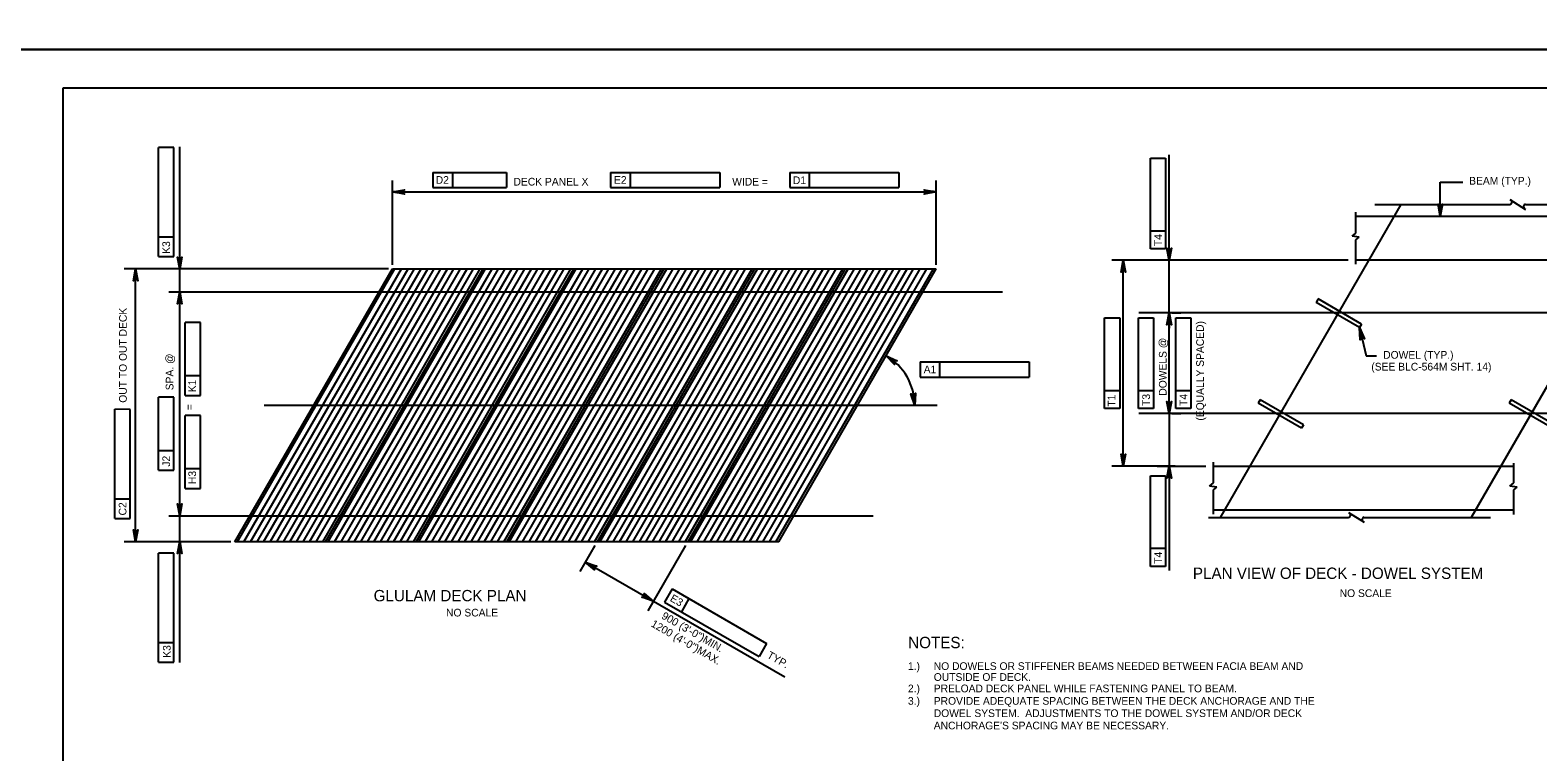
# Model space of a CAD drawing. Extents: x 638175 to 640495, y 294277 to 298435.
# Drawn here: x 639304 to 639891, y 296380 to 296661 of the extents above; entities that cross this region are included whole.
import ezdxf

# ---------------------------------------------------------------- set-up
doc = ezdxf.new("R2010")
doc.units = 0
for name, color, linetype in [('2', 7, 'Continuous'), ('3', 7, 'Continuous'), ('4', 7, 'Continuous'), ('5', 7, 'Continuous'), ('PLT-BNDY', 7, 'Continuous')]:
    doc.layers.add(name, color=color, linetype=linetype)

# ---------------------------------------------------------------- blocks, each defined once
blk = doc.blocks.new('D')
at = {"layer": '3'}
for p, q in [((-0.48575, 0.574125), (-0.574125, 0.48575)), ((0.52325, -0.6115), (-0.574125, 0.48575)), ((0.6115, -0.52325), (-0.48575, 0.574125)), ((0.6115, -0.52325), (0.52325, -0.6115))]:
    blk.add_line(p, q, dxfattribs=at)

msp = doc.modelspace()

# ---------------------------------------------------------------- linework, layer by layer
at = {"layer": '2'}
for p, q in [((639316.46, 296074.46), (639316.46, 296638.46)), ((639316.46, 296638.46), (640102.46, 296638.46)), ((639837.85, 296593.07), (639767.37, 296471.14)), ((639935.69, 296593.07), (639865.21, 296471.14)), ((639383.4, 296461.64), (639444.77, 296567.94)), ((639418.73, 296461.64), (639480.1, 296567.94)), ((639444.77, 296567.94), (639656.74, 296567.94)), ((639454.06, 296461.64), (639515.43, 296567.94)), ((639489.39, 296461.64), (639550.76, 296567.94)), ((639524.72, 296461.64), (639586.09, 296567.94)), ((639560.04, 296461.64), (639621.42, 296567.94)), ((639595.37, 296461.64), (639656.74, 296567.94)), ((639595.37, 296461.64), (639383.4, 296461.64))]:
    msp.add_line(p, q, dxfattribs=at)
at = {"layer": '3'}
for p, q in [((639880.33, 296595.01), (639886.49, 296591.14)), ((639820.34, 296581.91), (639820.34, 296590.01)), ((639820.34, 296588.45), (639937.41, 296588.45)), ((639827.73, 296593.07), (639880.26, 296593.07)), ((639886.48, 296593.07), (639938.55, 296593.07)), ((639818.8, 296580.72), (639820.34, 296581.91)), ((639821.56, 296580.3), (639818.8, 296580.72)), ((639820.34, 296579.21), (639821.56, 296580.3)), ((639820.34, 296569.79), (639820.34, 296579.21)), ((639937.41, 296571.33), (639820.34, 296571.33)), ((639926.24, 296550.81), (639735.71, 296550.84)), ((639813.03, 296550.13), (639813.82, 296551.49)), ((639790.35, 296510.9), (639791.14, 296512.26)), ((639905.36, 296511.58), (639735.7, 296511.61)), ((639764.83, 296484.54), (639764.83, 296492.64)), ((639764.83, 296491.08), (639881.91, 296491.08)), ((639881.91, 296484.54), (639881.91, 296492.27)), ((639763.29, 296483.35), (639764.83, 296484.54)), ((639766.05, 296482.93), (639763.29, 296483.35)), ((639764.83, 296481.83), (639766.05, 296482.93)), ((639880.37, 296483.35), (639881.91, 296484.54)), ((639883.12, 296482.93), (639880.37, 296483.35)), ((639881.91, 296481.83), (639883.12, 296482.93)), ((639764.83, 296472.41), (639764.83, 296481.83)), ((639881.91, 296472.22), (639881.91, 296481.83)), ((639762.88, 296471.14), (639817.36, 296471.14)), ((639881.91, 296473.95), (639764.83, 296473.95)), ((639817.43, 296473.08), (639823.59, 296469.21)), ((639823.57, 296471.14), (639872.73, 296471.14))]:
    msp.add_line(p, q, dxfattribs=at)
for centre, start, end in [((639880.26, 296593.98), 270, 60), ((639886.56, 296592.17), 95.32859, 237.86724), ((639817.36, 296472.05), 270, 60), ((639823.66, 296470.24), 95.32859, 237.86724)]:
    msp.add_arc(centre, 0.909, start, end, dxfattribs=at)
at = {"layer": '4'}
for p, q in [((639359.57, 296615.29), (639353.66, 296615.3)), ((639353.66, 296580.34), (639353.66, 296615.3)), ((639359.57, 296572.77), (639359.57, 296615.29)), ((639361.87, 296414.56), (639361.87, 296615.53)), ((639747.54, 296577.34), (639747.54, 296612.42)), ((639740.26, 296611.11), (639746.16, 296611.11)), ((639740.26, 296582.7), (639740.26, 296611.11)), ((639746.16, 296611.11), (639746.16, 296575.81)), ((639444.77, 296569.51), (639444.77, 296602.42)), ((639460.57, 296605.55), (639468.13, 296605.55)), ((639460.57, 296605.55), (639460.57, 296599.64)), ((639468.13, 296605.55), (639468.13, 296599.64)), ((639468.13, 296605.55), (639489.24, 296605.55)), ((639489.24, 296605.55), (639489.24, 296599.64)), ((639529.84, 296605.55), (639537.41, 296605.55)), ((639529.84, 296605.55), (639529.84, 296599.64)), ((639537.41, 296605.55), (639537.41, 296599.64)), ((639537.41, 296605.55), (639572.36, 296605.55)), ((639572.36, 296605.55), (639572.36, 296599.64)), ((639599.63, 296605.55), (639599.63, 296599.64)), ((639599.63, 296605.55), (639607.19, 296605.55)), ((639607.19, 296605.55), (639607.19, 296599.64)), ((639607.19, 296605.55), (639642.15, 296605.55)), ((639642.15, 296605.55), (639642.15, 296599.64)), ((639656.74, 296569.51), (639656.74, 296602.42)), ((639853.22, 296601.79), (639862.02, 296601.79)), ((639444.77, 296597.92), (639656.74, 296597.92)), ((639460.57, 296599.64), (639489.24, 296599.64)), ((639529.84, 296599.64), (639572.36, 296599.64)), ((639599.63, 296599.64), (639642.15, 296599.64)), ((639740.26, 296575.81), (639740.26, 296582.7)), ((639746.16, 296582.7), (639740.26, 296582.7)), ((639353.66, 296572.78), (639353.66, 296580.34)), ((639359.57, 296580.34), (639353.66, 296580.34)), ((639747.54, 296550.84), (639747.54, 296577.34)), ((639353.66, 296572.78), (639359.57, 296572.77)), ((639817.28, 296571.33), (639725.15, 296571.33)), ((639729.65, 296491.08), (639729.65, 296571.33)), ((639746.16, 296575.81), (639740.26, 296575.81)), ((639745.98, 296571.34), (639743.04, 296571.34)), ((639443.21, 296567.94), (639340.19, 296567.94)), ((639344.69, 296461.64), (639344.69, 296567.94)), ((639357.58, 296558.98), (639682.6, 296558.98)), ((639722.37, 296548.87), (639728.28, 296548.87)), ((639722.37, 296520.46), (639722.37, 296548.87)), ((639728.28, 296548.87), (639728.28, 296513.57)), ((639735.59, 296513.57), (639735.59, 296548.87)), ((639735.59, 296548.87), (639741.49, 296548.87)), ((639741.49, 296548.87), (639741.49, 296513.57)), ((639747.54, 296511.6), (639747.54, 296550.83)), ((639747.54, 296547.83), (639747.54, 296544.83)), ((639748.59, 296550.83), (639752.04, 296550.83)), ((639750.12, 296548.87), (639756.03, 296548.87)), ((639750.12, 296520.46), (639750.12, 296548.87)), ((639756.03, 296548.87), (639756.03, 296513.57)), ((639369.92, 296547.07), (639364.02, 296547.08)), ((639364.02, 296526.07), (639364.02, 296547.08)), ((639369.92, 296518.67), (639369.92, 296547.07)), ((639650.43, 296531.72), (639657.99, 296531.72)), ((639650.43, 296531.72), (639650.43, 296525.81)), ((639657.99, 296531.72), (639657.99, 296525.81)), ((639657.99, 296531.72), (639692.95, 296531.72)), ((639692.95, 296531.72), (639692.95, 296525.81)), ((639824.36, 296534.1), (639828.38, 296534.1)), ((639369.92, 296526.23), (639364.02, 296526.23)), ((639364.02, 296518.67), (639364.02, 296526.07)), ((639650.43, 296525.81), (639692.95, 296525.81)), ((639359.57, 296517.9), (639353.66, 296517.91)), ((639353.66, 296497.06), (639353.66, 296517.91)), ((639359.57, 296489.5), (639359.57, 296517.9)), ((639364.02, 296518.67), (639369.92, 296518.67)), ((639722.37, 296513.57), (639722.37, 296520.46)), ((639728.28, 296520.46), (639722.37, 296520.46)), ((639741.49, 296520.46), (639735.59, 296520.46)), ((639750.12, 296513.57), (639750.12, 296520.46)), ((639756.03, 296520.46), (639750.12, 296520.46)), ((639342.55, 296513.22), (639336.64, 296513.23)), ((639336.64, 296478.27), (639336.64, 296513.23)), ((639342.55, 296470.7), (639342.55, 296513.22)), ((639394.8, 296514.79), (639657.09, 296514.79)), ((639728.28, 296513.57), (639722.37, 296513.57)), ((639741.49, 296513.57), (639735.59, 296513.57)), ((639747.54, 296514.6), (639747.54, 296517.6)), ((639756.03, 296513.57), (639750.12, 296513.57)), ((639369.92, 296510.84), (639364.02, 296510.85)), ((639364.02, 296490.01), (639364.02, 296510.85)), ((639369.92, 296482.44), (639369.92, 296510.84)), ((639747.54, 296511.6), (639747.54, 296450.4)), ((639748.57, 296511.6), (639752.04, 296511.6)), ((639353.66, 296489.5), (639353.66, 296497.06)), ((639359.57, 296497.06), (639353.66, 296497.06)), ((639353.66, 296489.5), (639359.57, 296489.5)), ((639364.02, 296482.44), (639364.02, 296490.01)), ((639369.92, 296490), (639364.02, 296490.01)), ((639749.89, 296491.08), (639725.15, 296491.08)), ((639742.86, 296491.08), (639761.83, 296491.08)), ((639748.9, 296491.08), (639743.04, 296491.08)), ((639740.26, 296452.05), (639740.26, 296487.35)), ((639740.26, 296487.35), (639746.16, 296487.35)), ((639746.16, 296487.35), (639746.16, 296452.05)), ((639747.54, 296488.08), (639747.54, 296485.08)), ((639336.64, 296470.71), (639336.64, 296478.27)), ((639342.55, 296478.26), (639336.64, 296478.27)), ((639364.02, 296482.44), (639369.92, 296482.44)), ((639357.58, 296471.7), (639632.21, 296471.7)), ((639336.64, 296470.71), (639342.55, 296470.7)), ((639381.84, 296461.64), (639340.19, 296461.64)), ((639523.63, 296460.12), (639517.82, 296450.06)), ((639558.98, 296460.15), (639544.31, 296434.75)), ((639359.57, 296457.21), (639353.66, 296457.21)), ((639353.66, 296422.25), (639353.66, 296457.21)), ((639359.57, 296414.68), (639359.57, 296457.21)), ((639597.67, 296408.84), (639519.94, 296453.74)), ((639746.16, 296458.94), (639740.26, 296458.94)), ((639746.16, 296452.05), (639740.26, 296452.05)), ((639553.82, 296443.24), (639550.87, 296438.13)), ((639553.82, 296443.24), (639560.37, 296439.46)), ((639550.87, 296438.13), (639587.68, 296416.86)), ((639560.37, 296439.46), (639557.41, 296434.35)), ((639560.37, 296439.46), (639590.64, 296421.97)), ((639353.66, 296414.69), (639353.66, 296422.25)), ((639359.57, 296422.25), (639353.66, 296422.25)), ((639590.64, 296421.97), (639587.68, 296416.86)), ((639353.66, 296414.69), (639359.57, 296414.68))]:
    msp.add_line(p, q, dxfattribs=at)
for points in [[(639853.22, 296588.45), (639853.22, 296601.79)], [(639444.77, 296597.92), (639449.43, 296598.79), (639449.08, 296598.55), (639448.89, 296598.23), (639448.84, 296597.92), (639448.89, 296597.61), (639449.08, 296597.3), (639449.43, 296597.05), (639444.77, 296597.92), (639449.08, 296597.3), (639448.89, 296597.61), (639444.77, 296597.92), (639448.84, 296597.92), (639448.89, 296598.23), (639444.77, 296597.92), (639449.08, 296598.55)], [(639656.74, 296597.92), (639652.08, 296597.05), (639652.44, 296597.3), (639652.63, 296597.61), (639652.68, 296597.92), (639652.63, 296598.23), (639652.44, 296598.55), (639652.08, 296598.79), (639656.74, 296597.92), (639652.44, 296598.55), (639652.63, 296598.23), (639656.74, 296597.92), (639652.68, 296597.92), (639652.63, 296597.61), (639656.74, 296597.92), (639652.44, 296597.3)], [(639853.22, 296588.45), (639852.35, 296593.11), (639852.6, 296592.75), (639852.91, 296592.57), (639853.22, 296592.51), (639853.53, 296592.57), (639853.85, 296592.75), (639854.1, 296593.11), (639853.22, 296588.45), (639853.85, 296592.75), (639853.53, 296592.57), (639853.22, 296588.45), (639853.22, 296592.51), (639852.91, 296592.57), (639853.22, 296588.45), (639852.6, 296592.75)], [(639361.87, 296567.82), (639360.99, 296572.49), (639361.24, 296572.13), (639361.55, 296571.94), (639361.87, 296571.89), (639362.18, 296571.94), (639362.49, 296572.13), (639362.74, 296572.49), (639361.87, 296567.82), (639362.49, 296572.13), (639362.18, 296571.94), (639361.87, 296567.82), (639361.87, 296571.89), (639361.55, 296571.94), (639361.87, 296567.82), (639361.24, 296572.13)], [(639729.65, 296571.33), (639730.53, 296566.67), (639730.28, 296567.02), (639729.97, 296567.21), (639729.65, 296567.26), (639729.34, 296567.21), (639729.03, 296567.02), (639728.78, 296566.67), (639729.65, 296571.33), (639729.03, 296567.02), (639729.34, 296567.21), (639729.65, 296571.33), (639729.65, 296567.26), (639729.97, 296567.21), (639729.65, 296571.33), (639730.28, 296567.02)], [(639747.54, 296571.33), (639746.66, 296575.99), (639746.91, 296575.63), (639747.22, 296575.44), (639747.54, 296575.39), (639747.85, 296575.44), (639748.16, 296575.63), (639748.41, 296575.99), (639747.54, 296571.33), (639748.16, 296575.63), (639747.85, 296575.44), (639747.54, 296571.33), (639747.54, 296575.39), (639747.22, 296575.44), (639747.54, 296571.33), (639746.91, 296575.63)], [(639344.69, 296567.94), (639345.57, 296563.28), (639345.32, 296563.64), (639345.01, 296563.83), (639344.69, 296563.88), (639344.38, 296563.83), (639344.07, 296563.64), (639343.82, 296563.28), (639344.69, 296567.94), (639344.07, 296563.64), (639344.38, 296563.83), (639344.69, 296567.94), (639344.69, 296563.88), (639345.01, 296563.83), (639344.69, 296567.94), (639345.32, 296563.64)], [(639361.87, 296558.98), (639362.74, 296554.32), (639362.49, 296554.68), (639362.18, 296554.86), (639361.87, 296554.91), (639361.55, 296554.86), (639361.24, 296554.68), (639360.99, 296554.32), (639361.87, 296558.98), (639361.24, 296554.68), (639361.55, 296554.86), (639361.87, 296558.98), (639361.87, 296554.91), (639362.18, 296554.86), (639361.87, 296558.98), (639362.49, 296554.68)], [(639747.54, 296550.84), (639748.41, 296546.18), (639748.16, 296546.54), (639747.85, 296546.72), (639747.54, 296546.78), (639747.22, 296546.72), (639746.91, 296546.54), (639746.66, 296546.18), (639747.54, 296550.84), (639746.91, 296546.54), (639747.22, 296546.72), (639747.54, 296550.84), (639747.54, 296546.78), (639747.85, 296546.72), (639747.54, 296550.84), (639748.16, 296546.54)], [(639821.78, 296545.07), (639824.36, 296534.1)], [(639821.78, 296545.07), (639823.7, 296540.74), (639823.38, 296541.03), (639823.03, 296541.14), (639822.71, 296541.12), (639822.42, 296540.99), (639822.16, 296540.74), (639822, 296540.33), (639821.78, 296545.07), (639822.16, 296540.74), (639822.42, 296540.99), (639821.78, 296545.07), (639822.71, 296541.12), (639823.03, 296541.14), (639821.78, 296545.07), (639823.38, 296541.03)], [(639637.21, 296534.1), (639641.49, 296532.06), (639641.05, 296532.07), (639640.72, 296531.93), (639640.49, 296531.71), (639640.35, 296531.42), (639640.31, 296531.06), (639640.46, 296530.65), (639637.21, 296534.1), (639640.31, 296531.06), (639640.35, 296531.42), (639637.21, 296534.1), (639640.49, 296531.71), (639640.72, 296531.93), (639637.21, 296534.1), (639641.05, 296532.07)], [(639648.34, 296514.77), (639646.89, 296519.28), (639647.18, 296518.96), (639647.51, 296518.82), (639647.83, 296518.8), (639648.13, 296518.89), (639648.42, 296519.12), (639648.62, 296519.5), (639648.34, 296514.77), (639648.42, 296519.12), (639648.13, 296518.89), (639648.34, 296514.77), (639647.83, 296518.8), (639647.51, 296518.82), (639648.34, 296514.77), (639647.18, 296518.96)], [(639747.54, 296511.6), (639746.66, 296516.26), (639746.91, 296515.91), (639747.22, 296515.72), (639747.54, 296515.67), (639747.85, 296515.72), (639748.16, 296515.91), (639748.41, 296516.26), (639747.54, 296511.6), (639748.16, 296515.91), (639747.85, 296515.72), (639747.54, 296511.6), (639747.54, 296515.67), (639747.22, 296515.72), (639747.54, 296511.6), (639746.91, 296515.91)], [(639729.65, 296491.08), (639728.78, 296495.74), (639729.03, 296495.38), (639729.34, 296495.2), (639729.65, 296495.14), (639729.97, 296495.2), (639730.28, 296495.38), (639730.53, 296495.74), (639729.65, 296491.08), (639730.28, 296495.38), (639729.97, 296495.2), (639729.65, 296491.08), (639729.65, 296495.14), (639729.34, 296495.2), (639729.65, 296491.08), (639729.03, 296495.38)], [(639747.54, 296491.08), (639748.41, 296486.42), (639748.16, 296486.78), (639747.85, 296486.97), (639747.54, 296487.02), (639747.22, 296486.97), (639746.91, 296486.78), (639746.66, 296486.42), (639747.54, 296491.08), (639746.91, 296486.78), (639747.22, 296486.97), (639747.54, 296491.08), (639747.54, 296487.02), (639747.85, 296486.97), (639747.54, 296491.08), (639748.16, 296486.78)], [(639361.87, 296471.7), (639360.99, 296476.36), (639361.24, 296476), (639361.55, 296475.82), (639361.87, 296475.76), (639362.18, 296475.82), (639362.49, 296476), (639362.74, 296476.36), (639361.87, 296471.7), (639362.49, 296476), (639362.18, 296475.82), (639361.87, 296471.7), (639361.87, 296475.76), (639361.55, 296475.82), (639361.87, 296471.7), (639361.24, 296476)], [(639344.69, 296461.64), (639343.82, 296466.3), (639344.07, 296465.95), (639344.38, 296465.76), (639344.69, 296465.71), (639345.01, 296465.76), (639345.32, 296465.95), (639345.57, 296466.3), (639344.69, 296461.64), (639345.32, 296465.95), (639345.01, 296465.76), (639344.69, 296461.64), (639344.69, 296465.71), (639344.38, 296465.76), (639344.69, 296461.64), (639344.07, 296465.95)], [(639361.87, 296461.76), (639362.74, 296457.1), (639362.49, 296457.45), (639362.18, 296457.64), (639361.87, 296457.69), (639361.55, 296457.64), (639361.24, 296457.45), (639360.99, 296457.1), (639361.87, 296461.76), (639361.24, 296457.45), (639361.55, 296457.64), (639361.87, 296461.76), (639361.87, 296457.69), (639362.18, 296457.64), (639361.87, 296461.76), (639362.49, 296457.45)], [(639519.94, 296453.74), (639524.42, 296452.17), (639523.98, 296452.13), (639523.67, 296451.95), (639523.46, 296451.71), (639523.35, 296451.41), (639523.36, 296451.05), (639523.54, 296450.65), (639519.94, 296453.74), (639523.36, 296451.05), (639523.35, 296451.41), (639519.94, 296453.74), (639523.46, 296451.71), (639523.67, 296451.95), (639519.94, 296453.74), (639523.98, 296452.13)], [(639546.44, 296438.43), (639541.96, 296440.01), (639542.4, 296440.05), (639542.72, 296440.22), (639542.92, 296440.47), (639543.03, 296440.77), (639543.02, 296441.13), (639542.84, 296441.52), (639546.44, 296438.43), (639543.02, 296441.13), (639543.03, 296440.77), (639546.44, 296438.43), (639542.92, 296440.47), (639542.72, 296440.22), (639546.44, 296438.43), (639542.4, 296440.05)]]:
    msp.add_lwpolyline(points, dxfattribs=at)
for points in [[(639853.22, 296588.45), (639853.25, 296588.57), (639853.19, 296588.57)], [(639747.04, 296547.83), (639748.04, 296547.83), (639747.54, 296550.83)], [(639821.78, 296545.07), (639821.78, 296544.95), (639821.84, 296544.96)]]:
    msp.add_lwpolyline(points, close=True, dxfattribs=at)
msp.add_arc((639626.06, 296514.79), 22.28, 359.99937, 60.00065, dxfattribs=at)
at = {"layer": '5'}
for p, q in [((639384.36, 296461.64), (639445.73, 296567.94)), ((639386.92, 296461.64), (639448.29, 296567.94)), ((639389.47, 296461.64), (639450.85, 296567.94)), ((639392.03, 296461.64), (639453.4, 296567.94)), ((639394.59, 296461.64), (639455.96, 296567.94)), ((639397.15, 296461.64), (639458.52, 296567.94)), ((639399.7, 296461.64), (639461.08, 296567.94)), ((639402.26, 296461.64), (639463.63, 296567.94)), ((639404.82, 296461.64), (639466.19, 296567.94)), ((639407.37, 296461.64), (639468.75, 296567.94)), ((639409.93, 296461.64), (639471.3, 296567.94)), ((639412.49, 296461.64), (639473.86, 296567.94)), ((639415.05, 296461.64), (639476.42, 296567.94)), ((639417.6, 296461.64), (639478.98, 296567.94)), ((639419.69, 296461.64), (639481.06, 296567.94)), ((639422.24, 296461.64), (639483.62, 296567.94)), ((639424.8, 296461.64), (639486.17, 296567.94)), ((639427.36, 296461.64), (639488.73, 296567.94)), ((639429.92, 296461.64), (639491.29, 296567.94)), ((639432.47, 296461.64), (639493.85, 296567.94)), ((639435.03, 296461.64), (639496.4, 296567.94)), ((639437.59, 296461.64), (639498.96, 296567.94)), ((639440.15, 296461.64), (639501.52, 296567.94)), ((639442.7, 296461.64), (639504.07, 296567.94)), ((639445.26, 296461.64), (639506.63, 296567.94)), ((639447.82, 296461.64), (639509.19, 296567.94)), ((639450.37, 296461.64), (639511.75, 296567.94)), ((639452.93, 296461.64), (639514.3, 296567.94)), ((639455.02, 296461.64), (639516.39, 296567.94)), ((639457.57, 296461.64), (639518.94, 296567.94)), ((639460.13, 296461.64), (639521.5, 296567.94)), ((639462.69, 296461.64), (639524.06, 296567.94)), ((639465.24, 296461.64), (639526.62, 296567.94)), ((639467.8, 296461.64), (639529.17, 296567.94)), ((639470.36, 296461.64), (639531.73, 296567.94)), ((639472.92, 296461.64), (639534.29, 296567.94)), ((639475.47, 296461.64), (639536.84, 296567.94)), ((639478.03, 296461.64), (639539.4, 296567.94)), ((639480.59, 296461.64), (639541.96, 296567.94)), ((639483.14, 296461.64), (639544.52, 296567.94)), ((639485.7, 296461.64), (639547.07, 296567.94)), ((639488.26, 296461.64), (639549.63, 296567.94)), ((639490.34, 296461.64), (639551.72, 296567.94)), ((639492.9, 296461.64), (639554.27, 296567.94)), ((639495.46, 296461.64), (639556.83, 296567.94)), ((639498.02, 296461.64), (639559.39, 296567.94)), ((639500.57, 296461.64), (639561.94, 296567.94)), ((639503.13, 296461.64), (639564.5, 296567.94)), ((639505.69, 296461.64), (639567.06, 296567.94)), ((639508.24, 296461.64), (639569.62, 296567.94)), ((639510.8, 296461.64), (639572.17, 296567.94)), ((639513.36, 296461.64), (639574.73, 296567.94)), ((639515.92, 296461.64), (639577.29, 296567.94)), ((639518.47, 296461.64), (639579.84, 296567.94)), ((639521.03, 296461.64), (639582.4, 296567.94)), ((639523.59, 296461.64), (639584.96, 296567.94)), ((639525.67, 296461.64), (639587.04, 296567.94)), ((639528.23, 296461.64), (639589.6, 296567.94)), ((639530.79, 296461.64), (639592.16, 296567.94)), ((639533.34, 296461.64), (639594.72, 296567.94)), ((639535.9, 296461.64), (639597.27, 296567.94)), ((639538.46, 296461.64), (639599.83, 296567.94)), ((639541.02, 296461.64), (639602.39, 296567.94)), ((639543.57, 296461.64), (639604.94, 296567.94)), ((639546.13, 296461.64), (639607.5, 296567.94)), ((639548.69, 296461.64), (639610.06, 296567.94)), ((639551.24, 296461.64), (639612.62, 296567.94)), ((639553.8, 296461.64), (639615.17, 296567.94)), ((639556.36, 296461.64), (639617.73, 296567.94)), ((639558.92, 296461.64), (639620.29, 296567.94)), ((639561, 296461.64), (639622.37, 296567.94)), ((639563.56, 296461.64), (639624.93, 296567.94)), ((639566.12, 296461.64), (639627.49, 296567.94)), ((639568.67, 296461.64), (639630.04, 296567.94)), ((639571.23, 296461.64), (639632.6, 296567.94)), ((639573.79, 296461.64), (639635.16, 296567.94)), ((639576.34, 296461.64), (639637.72, 296567.94)), ((639578.9, 296461.64), (639640.27, 296567.94)), ((639581.46, 296461.64), (639642.83, 296567.94)), ((639584.02, 296461.64), (639645.39, 296567.94)), ((639586.57, 296461.64), (639647.94, 296567.94)), ((639589.13, 296461.64), (639650.5, 296567.94)), ((639591.69, 296461.64), (639653.06, 296567.94)), ((639594.24, 296461.64), (639655.62, 296567.94))]:
    msp.add_line(p, q, dxfattribs=at)
at = {"layer": 'PLT-BNDY'}
for points in [[(639276.46, 297247.46), (640117.46, 297247.46), (640117.46, 296653.46), (639276.46, 296653.46)], [(639276.46, 296653.46), (640117.46, 296653.46), (640117.46, 296059.46), (639276.46, 296059.46)]]:
    msp.add_lwpolyline(points, close=True, dxfattribs=at)

# ---------------------------------------------------------------- block references
at = {"layer": '4', "xscale": 12.59905511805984, "yscale": 12.599055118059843, "rotation": 14.970848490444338}
for p in [(639813.42, 296550.81), (639790.74, 296511.58), (639888.58, 296511.58)]:
    msp.add_blockref('D', p, dxfattribs=at)

# ---------------------------------------------------------------- texts
at = {"layer": '4'}
for s, rotation, p in [('D2', 359.93823, (639461.65, 296601.09)), ('E2', 359.93823, (639531.13, 296601.09)), ('D1', 359.93823, (639600.87, 296600.98)), ('K3', 89.93823, (639358.11, 296573.8)), ('T4', 90, (639744.73, 296576.8)), ('OUT TO OUT DECK', 90, (639341.23, 296515.79)), ('(EQUALLY SPACED)', 90, (639761.07, 296508.83)), ('DOWELS @', 90, (639746.54, 296518.54)), ('SPA. @', 90, (639359.42, 296520.64)), ('A1', 359.93823, (639651.86, 296527.27)), ('K1', 89.93823, (639368.23, 296519.87)), ('T1', 90, (639726.59, 296514.26)), ('T3', 90, (639740.06, 296514.55)), ('T4', 90, (639754.6, 296514.56)), ('=', 90, (639367.14, 296512.87)), ('J2', 89.93823, (639358.11, 296490.89)), ('H3', 89.93823, (639368.23, 296484.09)), ('C2', 89.93823, (639341.1, 296471.88)), ('T4', 90, (639744.73, 296453.03)), ('E3', 329.92285, (639552.72, 296438.73)), ('1200 (4\'-0")MAX.', 329.97913, (639545.28, 296428.82)), ('900 (3\'-0")MIN.', 329.97913, (639549.42, 296431.91)), ('K3', 89.93823, (639358.35, 296416.44)), ('TYP.', 330.58675, (639590.49, 296416.56))]:
    msp.add_text(s, height=3, rotation=rotation, dxfattribs=at).set_placement(p)
for s, height, p in [('DECK PANEL X', 3, (639491.97, 296600.42)), ('WIDE =', 3, (639577.22, 296600.42)), ('BEAM (TYP.)', 3, (639864.47, 296600.76)), ('DOWEL (TYP.)', 3, (639830.96, 296532.95)), ('(SEE BLC-564M SHT. 14)', 3, (639826.33, 296528.35)), ('PLAN VIEW OF DECK - DOWEL SYSTEM', 4.4292, (639756.78, 296447.14)), ('GLULAM DECK PLAN', 4.4292, (639437.46, 296438.42)), ('NO SCALE', 3, (639814, 296440.09)), ('NO SCALE', 3, (639465.69, 296432.52)), ('NOTES:', 4.429, (639645.81, 296420.16)), ('1.)', 3, (639645.72, 296411.68)), ('NO DOWELS OR STIFFENER BEAMS NEEDED BETWEEN FACIA BEAM AND ', 3, (639655.78, 296411.68)), ('2.)', 3, (639645.72, 296402.98)), ('OUTSIDE OF DECK.', 3, (639655.78, 296407.43)), ('3.)', 3, (639645.72, 296398.13)), ('PRELOAD DECK PANEL WHILE FASTENING PANEL TO BEAM.', 3, (639655.78, 296402.98)), ('PROVIDE ADEQUATE SPACING BETWEEN THE DECK ANCHORAGE AND THE ', 3, (639655.78, 296398.13)), ('DOWEL SYSTEM.  ADJUSTMENTS TO THE DOWEL SYSTEM AND/OR DECK', 3, (639655.78, 296393.33)), ("ANCHORAGE'S SPACING MAY BE NECESSARY.", 3, (639655.78, 296388.53))]:
    msp.add_text(s, height=height, dxfattribs=at).set_placement(p)

doc.saveas('drawing.dxf')
